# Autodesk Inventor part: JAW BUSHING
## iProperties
Created: 2006-07
Part Number: JAW BUSHING
Material: Steel
Document SubType Name: Modeling
Designer: rollin42
Density: 7.85 g/cm^3
Author: rollin42
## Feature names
1. Extrusion1
2. Extrusion2
3. Hole1
4. Extrusion3
